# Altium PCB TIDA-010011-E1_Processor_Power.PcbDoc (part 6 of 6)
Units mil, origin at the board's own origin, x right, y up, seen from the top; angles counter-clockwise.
Board outline 4921.26 x 4921.26 mil, 4 copper layers (Top Layer, Gnd layer, Gnd/Pwr layer, Bottom Layer), stack 62.634 mil thick; 631 components, 254 nets, 1751 pads, 757 vias.
Unrouted connection lines stored in the file: 1.
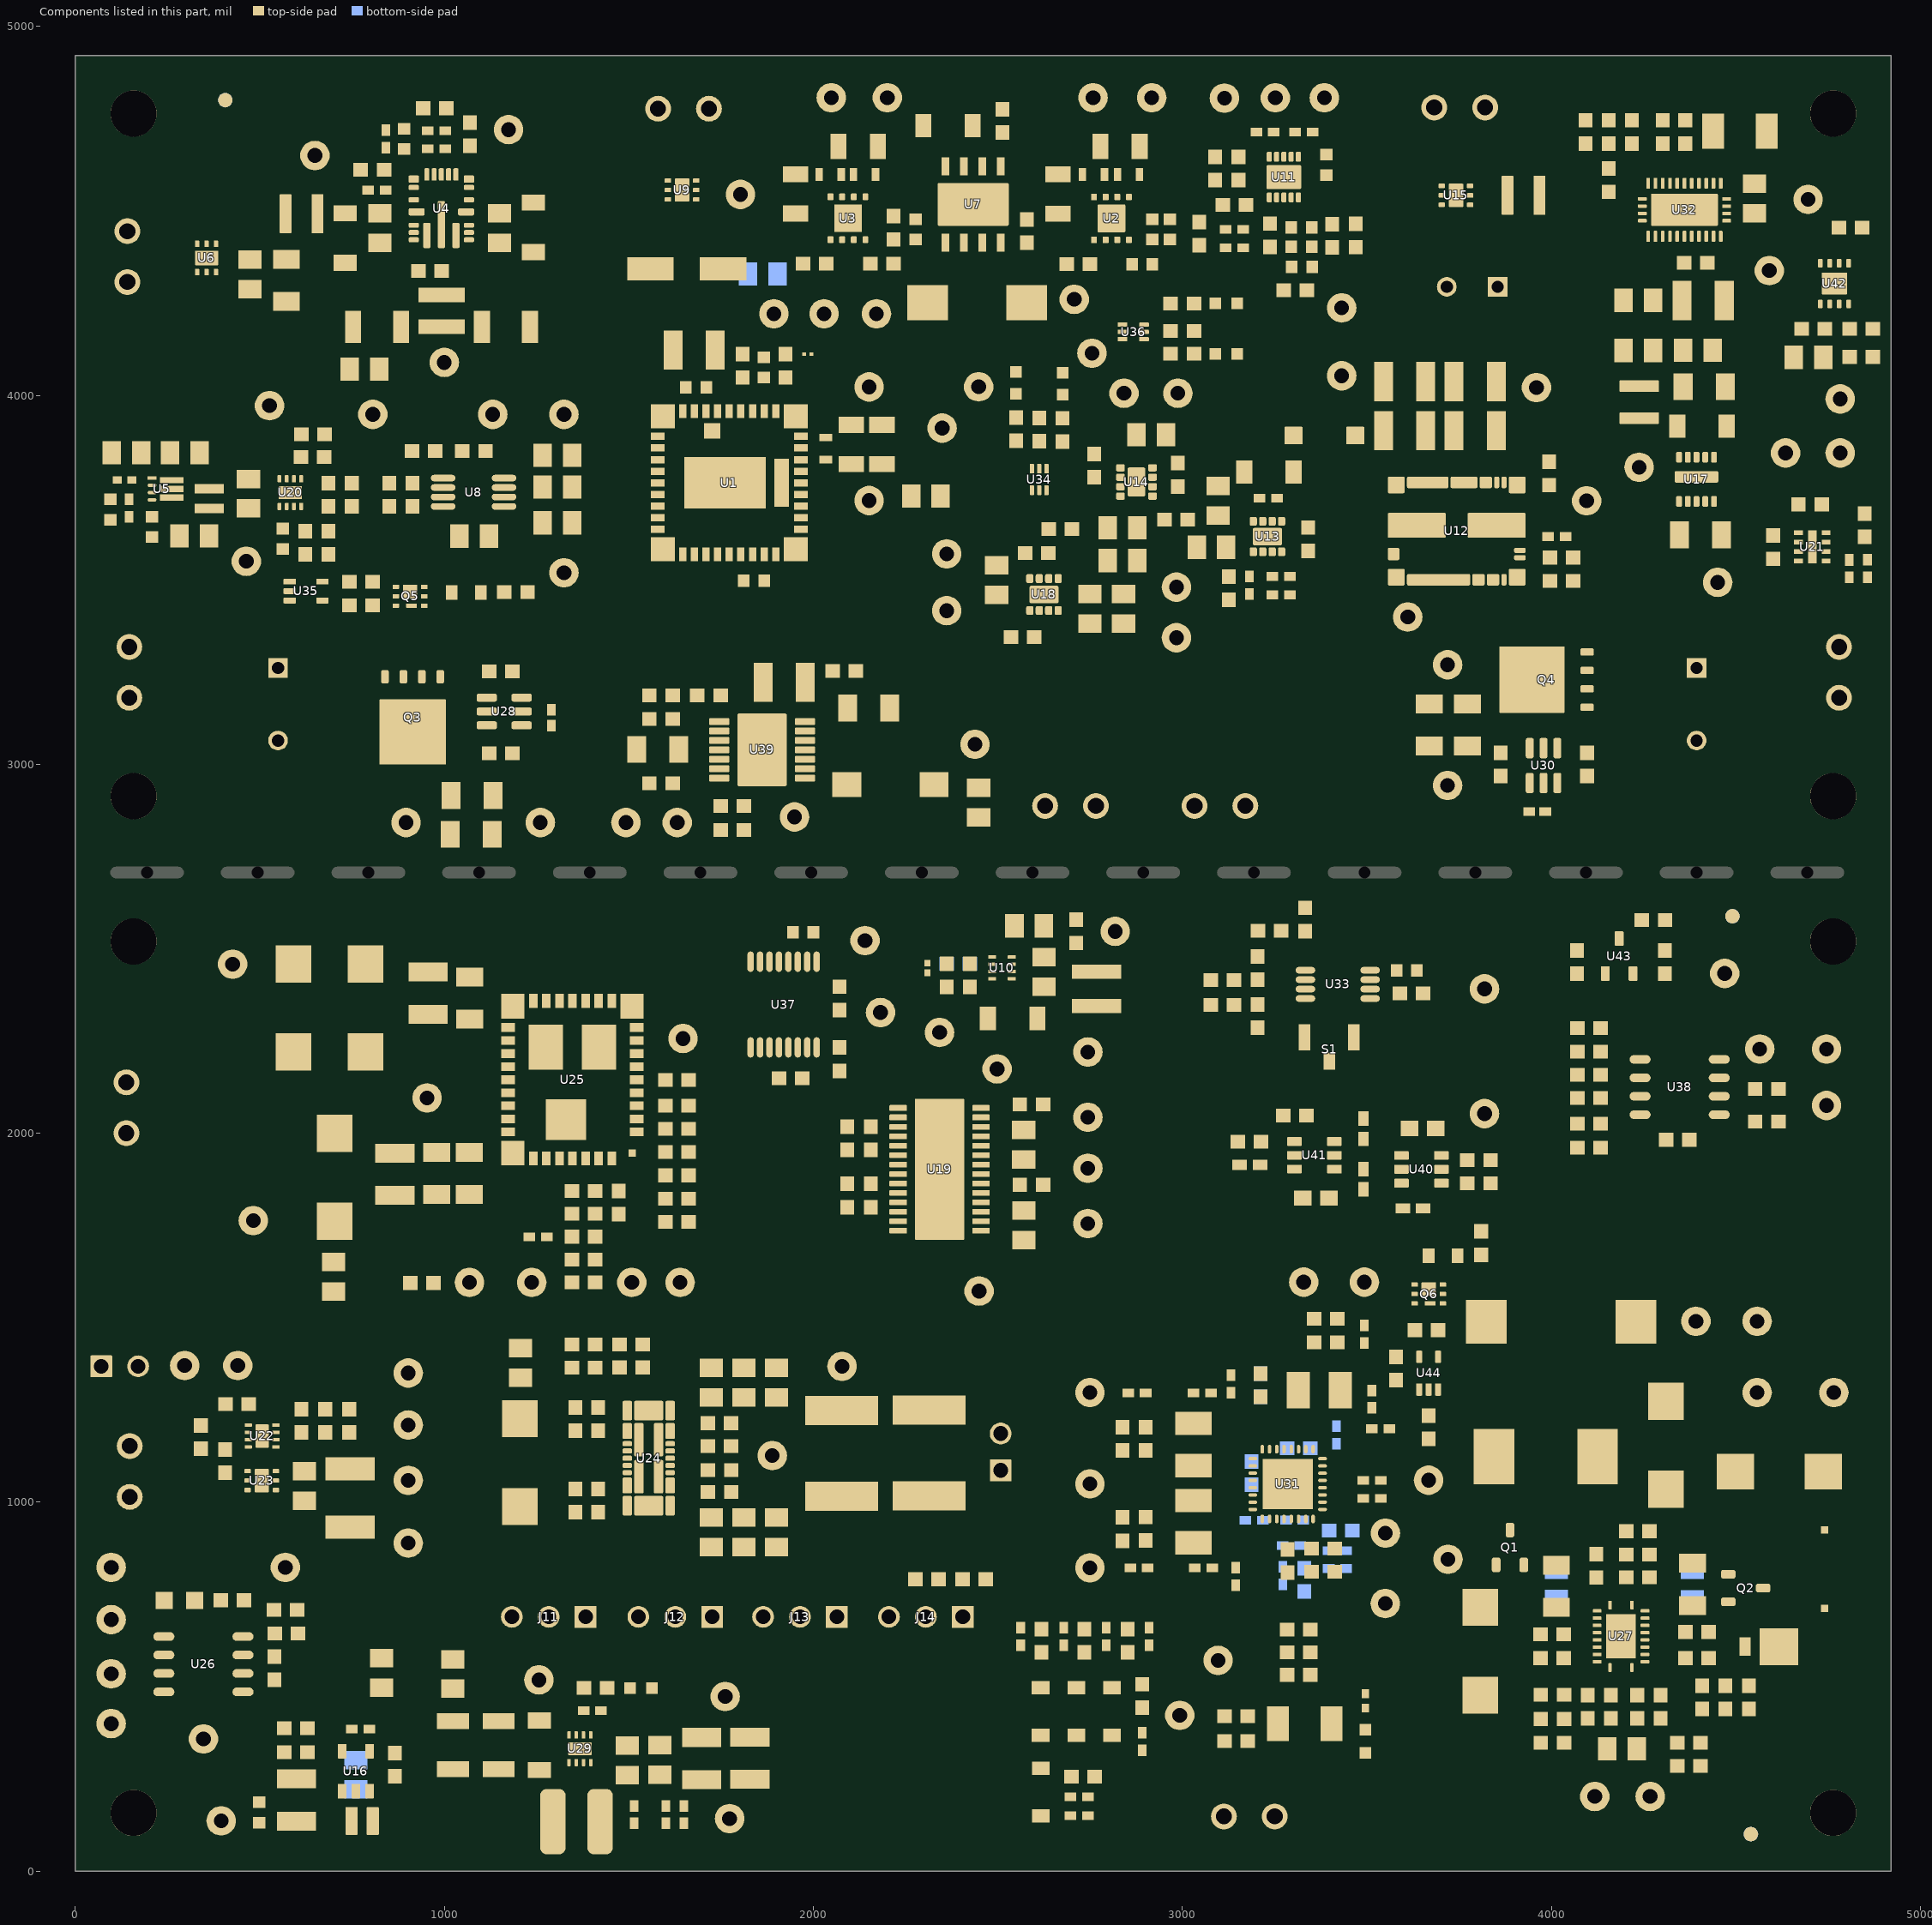
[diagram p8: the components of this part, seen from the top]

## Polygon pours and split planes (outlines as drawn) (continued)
5I_3P3V on Top Layer "n" (solid, remove dead copper, pour order 104): 4593,3827 4593,3723 4618,3698 4644,3672 4644,3658 4644,3624 4647,3621 4682,3621 4684,3623 4684,3668.66 4691,3675.66 4691,3885 4682,3894 4601,3894 4593,3886
NetC149_2 on Top Layer "n" (solid, pour order 108): 22 vertices, not listed, extent 4336,4558 4468,4803.5
GND on Top Layer "n" (solid, remove dead copper, pour order 110): 33 vertices, not listed, extent 4126,4199 4643,4576
3.3V_H on Top Layer "gn" (solid, pour order 200): 511,3743 421,3743 418,3746 418,3900 425,3907 515,3907 522,3900 522,3749 516,3743
5V_EFUSE_OUT on Top Layer "gn" (solid, remove dead copper, pour order 260): 30 vertices, not listed, extent 593,552 1093,1596
GND_5V on Top Layer "gn" (solid, remove dead copper, pour order 262): 4540,554 4534,548 4531,545 4482,545 4413,545 4405,553 4405,671 4414,680 4415,681 4500,681 4532,681 4540,673
NetC74_1 on Top Layer "gn" (solid, remove dead copper, pour order 304): 21 vertices, not listed, extent 3350,1130 3464,1525
GND_5V on Top Layer "gn" (solid, remove dead copper, pour order 306): 3379,1489 3379,1637 3372,1644 3283,1644 3277,1638 3277,1414 3281,1410 3374,1410 3379,1415
NetL13_1 on Top Layer "gn" (solid, remove dead copper, pour order 308): 3343,1387 3288,1387 3283,1382 3278,1377 3278,1321 3278,1240 3296,1222 3341.56,1222 3345.9,1226.34 3349,1229.44 3349,1277 3349,1382 3344,1387
PMIC_IN on Top Layer "gn" (solid, remove dead copper, pour order 310): 3325,330 3325,889 3328,892 3379,892 3379,769 3474,674 3474,530 3461,517 3461,329 3456.84,324.84 3330.16,324.84
NetL14_1 on Top Layer "gn" (solid, pour order 324): 2985.21,1130.25 3107.75,1130.25 3113,1125 3113,1071 3108,1066 2956,1066 2951,1071 2951,1127.54 2953.72,1130.25
NetL10_1 on Top Layer "gn" (solid, pour order 340): 1312,225 1258,225 1252,219 1252,47 1258,41 1264,35 1328,35 1333,40 1333,204 1318,219
NetC129_1 on Top Layer "gn" (solid, pour order 342): 55 vertices, not listed, extent 815,2762 4036,3424
24V_S on Top Layer "gn" (solid, pour order 344): 23 vertices, not listed, extent 3807,3748 4222,4623
1.2V/1A on Top Layer "gn" (solid, pour order 388): 2585,2346 2687,2346 2692,2351 2692,2371 2695,2374 2847,2374 2853,2368 2853,2198 2823,2168 2646,2168 2597,2217 2583,2231 2583,2294 2583,2344
GND_5V on Top Layer "gn" (solid, pour order 390): 26 vertices, not listed, extent 2287,2231 2661,2425
GND_5V on Top Layer "gn" (solid, pour order 396): 2205,2553 2205,2503 2216,2492 2285,2492 2312.26,2519.26 2400.74,2519.26 2493.67,2519.26 2498,2523.58 2498,2557 2490,2565 2217,2565
NetC7_1 on Top Layer "gn" (solid, pour order 398): 2316,3684 2316,3826 2326,3836 2441,3836 2453,3824 2453,3663 2447.67,3657.67 2322.33,3657.67 2316,3664
NetC67_1 on Top Layer "gn" (solid, pour order 400): 1247,1388 1126,1388 1120,1394 1118,1396 1118,1401 1118,1476 1127,1485 1280,1485 1294,1471 1294,1396 1286,1388
NetC186_1 on Top Layer "vo" (solid, pour order 404): 778,385 778,515 789,526 894,526 905,515 905,310 895,300 784,300 778,306
5V_EFUSE_OUT on Top Layer "vo" (solid, pour order 406): 975,552 789,552 779,562 779,622 786,629 951,629 968,646 973,651 990,651 990,552 989,551
NetL19_1 on Top Layer "vo" (solid, pour order 408): 783,204 783,84 788,79 831,79 835,83 835,219 812.02,241.98 787.98,241.98 783,237
GND on Bottom Layer "n" (solid, remove dead copper, pour order 384): 675,2759 40,2759 20.39,2778.61 20.39,4855.65 63.74,4899 4837,4899 4894,4842 4894,2820 4833,2759 4338,2759
GND on Bottom Layer "n" (solid, remove dead copper, pour order 376): 32 vertices, not listed, extent 1434.67,3686.67 1871.67,4832.67
NetC1_1 on Bottom Layer "n" (solid, remove dead copper, pour order 354): 30 vertices, not listed, extent 1673.67,3859.12 1853,4832.67
GND on Bottom Layer "n" (solid, remove dead copper, pour order 368): 49 vertices, not listed, extent 3536,3476 3930.71,4837
NetJ3_1 on Bottom Layer "n" (solid, pour order 360): 3770,4687 3770,4800 3770,4825 3779,4834 3782,4837 3832,4837 3891.34,4837 3899.34,4829 3899.34,4483.34 3893,4477 3775,4477 3770,4482
GND_5V on Bottom Layer "gn" (solid, remove dead copper, pour order 338): 915,2644 42,2644 23,2625 23,50 42,31 4842,31 4899,88 4899,2603 4858,2644
NetC177_1 on Bottom Layer "gn" (solid, remove dead copper, pour order 336): 17 vertices, not listed, extent 3155,109 3289,482
NetC18_1 on Bottom Layer "n" (solid, remove dead copper, pour order 328): 22 vertices, not listed, extent 80,4339 619.38,4576
NetC145_1 on Bottom Layer "gn" (solid, remove dead copper, pour order 188): 1780,1914 1979,1715 2023,1715 2112,1715 2119,1722 2119,1816 2115,1820 2113,1822 2021,1822 1891,1952 1891,2099 1880,2110 1788,2110 1780,2102
AGND on Bottom Layer "n" (solid, remove dead copper, pour order 40): 23 vertices, not listed, extent 1508.67,3465.67 2012.67,3648.67
NetC20_1 on Bottom Layer "n" (solid, remove dead copper, pour order 16): 597,4706 1072,4706 1138,4640 1283,4640 1296,4627 1296,4573 1296,4470 1288,4462 1112.74,4462 1045,4529.74 916.94,4529.74 605.26,4529.74 591,4544 591,4700
12VOUT on Bottom Layer "n" (solid, remove dead copper, pour order 88): 24 vertices, not listed, extent 3378,3600 3721,4109
5V on Bottom Layer "n" (solid, remove dead copper, pour order 28): 2206.67,3657.67 1899.67,3657.67 1894.06,3663.27 1894.06,3851.25 1930.09,3851.25 1938.67,3842.67 1938.67,3799.33 1950,3788 2208,3788 2224.67,3771.33 2224.67,3675.67
24V_S on Bottom Layer "n" (solid, remove dead copper, pour order 248): 18 vertices, not listed, extent 3807.68,3748 4043,4623
GND_5V on Gnd layer "gn" (solid, remove dead copper, pour order 274): 915,2644 42,2644 23,2625 23,50 42,31 4842,31 4899,88 4899,2603 4858,2644
GND on Gnd layer "n" (solid, remove dead copper, pour order 142): 675,2759 40,2759 20.39,2778.61 20.39,4855.65 63.74,4899 4837,4899 4894,4842 4894,2820 4833,2759 4338,2759
GND on Gnd/Pwr layer "gn" (solid, remove dead copper, pour order 370): 40,2759 20.39,2778.61 20.39,3324 74,3377.61 1382.61,3377.61 1433,3428 1433,4882 1450,4899 4836.65,4899 4894,4841.65 4894,2820 4833,2759 40,2759
NetC7_1 on Gnd/Pwr layer "gn" (solid, remove dead copper, pour order 0): 18 vertices, not listed, extent 1894.06,3658 2995,4895.77
GND on Gnd/Pwr layer "n" (solid, remove dead copper, pour order 362): 49 vertices, not listed, extent 3536,3476 3930.71,4837
NetJ3_1 on Gnd/Pwr layer "n" (solid, pour order 358): 3770,4687 3770,4800 3770,4825 3779,4834 3782,4837 3832,4837 3891.34,4837 3899.34,4829 3899.34,4483.34 3893,4477 3775,4477 3770,4482
GND on Gnd/Pwr layer "n" (solid, remove dead copper, pour order 356): 32 vertices, not listed, extent 1434.67,3686.67 1871.67,4832.67
NetC1_1 on Gnd/Pwr layer "n" (solid, remove dead copper, pour order 352): 30 vertices, not listed, extent 1673.67,3859.12 1858.67,4832.67
5V_H on Gnd/Pwr layer "gn" (solid, remove dead copper, pour order 202): 1383,4028 33,4028 21,4040 21,4889.26 31.74,4900 1400,4900 1410,4890 1410,4055
3.3V_H on Gnd/Pwr layer "gn" (solid, remove dead copper, pour order 212): 69,4004 22,3957 22,3450 41,3431 74,3398 862,3398 1366,3398 1411,3443 1411,3976 1383,4004
AGND on Gnd/Pwr layer "n" (solid, pour order 224): 23 vertices, not listed, extent 1508.67,3465.67 2012.67,3648.67
12VOUT on Gnd/Pwr layer "n" (solid, remove dead copper, pour order 228): 24 vertices, not listed, extent 3378,3600 3721,4109
24V_S on Gnd/Pwr layer "n" (solid, remove dead copper, pour order 240): 18 vertices, not listed, extent 3807.68,3748 4043,4623
SVC_5V on Gnd/Pwr layer "n" (solid, remove dead copper, pour order 252): 20 vertices, not listed, extent 4510,4479 4749,4819
5I_3P3V on Gnd/Pwr layer "gn" (solid, remove dead copper, pour order 258): 4593,3886 4593,3491 4605,3479 4630,3479 4890,3479 4901,3490 4901,3902 4890,3913 4603,3913 4593,3903
PMIC_IN on Gnd/Pwr layer "gn" (solid, remove dead copper, pour order 312): 17 vertices, not listed, extent 2537,31 4899,1697
3.6I_3P3V on Gnd/Pwr layer "gn" (solid, remove dead copper, pour order 316): 17 vertices, not listed, extent 1783,1495 4899,2644
NetC67_1 on Gnd/Pwr layer "gn" (solid, pour order 326): 18 vertices, not listed, extent 23,31 2665,2644

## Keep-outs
Keep-Out Layer:
  the board outline again, w10
  text ".Layer_Name" at 179.39,-1385.08 h60

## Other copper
Top Layer:
  text ".Layer_Name" at 179.39,-1385.08 h60
Gnd layer:
  text "'.Layer_Name'" at 200,-1380 h60
Gnd/Pwr layer:
  pour cut-out: 2528,4566 2537,4557 2537,4479 2524,4466 2327,4466 2320,4473 2320,4561 2325,4566
  pour cut-out: 2137.29,4261.23 2200.7,4261.23 2208.5,4253.44 2208.5,4193.44 2195.5,4180.44 2141.5,4180.44 2128.5,4193.44 2128.5,4252.44
  pour cut-out: 4751.79,3883.05 4815.21,3883.05 4823,3875.25 4823,3815.25 4810,3802.25 4756,3802.25 4743,3815.25 4743,3874.25
  pour cut-out: 2726.86,4845.79 2790.28,4845.79 2798.07,4838 2798.07,4778 2785.07,4765 2731.07,4765 2718.07,4778 2718.07,4837
  pour cut-out: 2014.79,4846.79 2078.21,4846.79 2086,4839 2086,4779 2073,4766 2019,4766 2006,4779 2006,4838
  pour cut-out: 2201.67,4096.67 2212.67,4085.67 2212.67,3950.67 2199.67,3937.67 1996.67,3937.67 1983.67,3950.67 1983.67,4090.67 1989.67,4096.67
  text "'.Layer_Name'" at 207,-1387 h60
Bottom Layer:
  text ".Layer_Name" at 179.39,-1385.08 h60

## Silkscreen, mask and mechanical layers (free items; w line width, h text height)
Top Overlay:
  lines w6: 286.31,3791.54 303.54,3791.54 ; 525,3651 525,3666 537.01,3678.01 537.01,3693.94 ; 713.27,3790.24 713.27,3794.27 726,3807 726,3813 ; 746.65,3616.35 746.65,3539 835,3539 ; 748,3643 748,3657 879,3657 879,3553 ; 757,3633 729,3633 ; 833.98,3521.53 843.53,3521.53 ; 918,4817 918,4863 ; 1151,3202.06 1151,3084.95 1170.95,3084.95 1170.95,3202 1151.05,3202 ; 1869,4017 1869,4024 ; 2409,4061 2409,4074 ; 2665,2351 2665,2363 ; 2694.6,4133.4 2703.5,4133.4 ; 2741.71,4207.71 2741.71,4217.31 ; 2752,3597 2764,3609 2764,3612 ; 3090,4301 3090,4366 ; 3124.92,4674.45 3124.92,4684.92 ; 3198,4846 3208,4836 ; 3238,4312 3236,4310 ; 3266,4154 3266,4242 ; 3368,4484 3368,4490 3284,4490 3273,4479 3273,4347 3236,4310 ; 3375,4364 3375,4250 3361,4236 3361,4062 3236,4062 3236,4270 3236,4310 ; 3392,766 3392,783 ; 3692,1009 3731,970 3769,970 ; 4071.8,504.98 4071.8,520.2 4345.2,520.2 4364,539 4903,539 4903,367 4578,367 4559.98,385.02 4323.2,385.02 ; 4146,952 4158,940 4158,894 4166.8,885.2 4175.02,885.2 ; 4294.98,754.02 4294.98,768.8 ; 4630,396 4581,396 ; 729,3633 729,3631 736,3624 736,3640 729,3633 ; 918,4863 919,4863 925,4857 912,4857 918,4863 ; 3090,4366 3096,4360 3084,4360 3090,4366 ; 3266,4242 3267,4242 3275,4234 3258,4234 3266,4242 ; 3392,783 3387,778 3399,778 3394,783 3392,783 ; 4581,396 4589,388 4589,404 4581,396 ; 3919.95,2990.58 4038,2990.58 4038.06,2990.64 4038.06,3010.53 3919.95,3010.53 3919.95,2990.58
  lines w10: 194,2706.42 -0.42,2706.42 4920.42,2706.42
  text "1.8V" at 2873,4873 h30
  text "3.3V" at 2157,4871 h30
  text "GND" at 2698,4871 h30
  text "DDR_REF" at 3340,4870 h30
  text "GND" at 2007,4869 h30
  text "PG3" at 3069,4866 h30
  text "EN" at 3198,4846 h30 r90
  text "RESET" at 1236,4710 h30
  text "SVC_5V" at 4650,4594 h30
  text "GND" at 4519,4400 h30
  text "VTT_DDR" at 3387,4301 h30
  text "UVLO" at 1883,4288 h30 r90
  text "PG2" at 1992,4283 h30
  text "GND" at 2132,4283 h30
  text "VREF" at 2641,4170 h30
  text "12VOUT" at 3370.74,4116.58 h30
  text "PG1" at 2623,4115 h30
  text "VSENSE" at 2345,4083 h30
  text "5V_H" at 946,3995 h30
  text "GND" at 2240,3986 h30 r90
  text "SD" at 2319,3973 h30
  text "1.2V_CPM" at 3054,3964 h30
  text "GND" at 2781,3943 h30 r90
  text "3.3V_H" at 867,3939 h30
  text "5I_3P3V" at 4542,3906 h30
  text "FLAG1" at 1415,3904 h30 r90
  text "FLAG2" at 1221,3898 h30 r90
  text "GND" at 4873,3805 h30 r90
  text "PG4" at 4202,3711 h30
  text "5V" at 2112,3618 h30
  text "1.8V_CPM" at 2094,3501 h30
  text "FLAG3" at 1285,3423 h30
  text "SW" at 3481,3399 h30
  text "GND" at 2220,3359 h30
  text "GND" at 3571,2925.53 h30
  text "GND" at 748,2819 h30
  text "GND" at 2042,2812 h30 r90
  text "'.PRJ_Number'" at 3277,2766 h50
  text "PM_2.5V_OUT" at 317,2568 h30
  text "PG" at 2882,2532 h30
  text "SS/TR" at 1583,2355 h30
  text "RESET2" at 3686,2295 h30
  text "ALERT" at 4484,2289 h30
  text "EN" at 2163,2234 h30
  text "SCL" at 4812,2215 h30
  text "1.2V/1A" at 2809,2188 h30
  text "GND_5V" at 2156,2186 h30
  text "RESET1" at 2281,2128 h30
  text "GND_5V" at 717,2096 h30
  text "SDA" at 4810,2063 h30
  text "3.3I_1P8V" at 2812,2029 h30
  text "GND_5V" at 2805,1844 h30
  text "5V_EFUSE" at 251,1836 h30
  text "GND_5V" at 3213,1663 h30
  text "PMIC_1V5" at 3399,1662 h30
  text "3.6I_3P3V" at 2697,1648 h30
  text "GND_5V" at 4496,1597 h30
  text "VOUT1" at 4328,1592 h30
  text "RT/CLK" at 1704,1583 h30
  text "GND_5V" at 2516,1555 h30
  text "VADJ" at 1458,1504 h30
  text "UVLO" at 240,1474 h30
  text "DV/DT" at 386,1474 h30
  text "PG" at 1037,1468 h30
  text "INH" at 1205,1467 h30
  text "VOUT2" at 4708,1402 h30
  text "PMIC_3V3" at 2628,1367 h30
  text "PM_3.6V_OUT" at 2144,1352 h30
  text "ILM" at 967,1299 h30
  text "GND_5V" at 4487,1222 h30 r90
  text "GND_5V" at 1815,1186 h25
  text "FLT" at 966,1158 h30
  text "GND_5V" at 2525,987 h30
  text "5V_EFUSE" at 836,965 h30
  text "PMIC_RESET" at 3783,954 h30
  text "PMIC_IN" at 3631,907 h30
  text "PMIC_1V1" at 2476,849 h30
  text "GND_5V" at 846,796 h30
  text "PMIC_1V8_1" at 3487,741.73 h25 r90
  text "PG_2A" at 1184,584 h30
  text "GND_5V" at 3027,538 h30 r90
  text "GND_5V" at 1823,471 h30
  text "PMIC_1V8_2" at 3587,432 h25 r90
  text "GND_5V" at 3880,204 h30
  text "VCC_1.8V_2A" at 1840,109 h30
  text "VOUT3" at 4211,104 h30
  text "3.3V" at 302,39 h30
  text "'.PRJ_Number'" at 1541,31 h50
  text ".Layer_Name" at 179.39,-1385.08 h60
Bottom Overlay:
  text ".Layer_Name" at 179.39,-1385.08 h60
Top Paste:
  text ".Layer_Name" at 179.39,-1385.08 h60
Bottom Paste:
  text ".Layer_Name" at 179.39,-1385.08 h60
Top Solder:
  text ".Layer_Name" at 179.39,-1385.08 h60
  text ".Layer_Name" at 179.39,-1385.08 h60
Bottom Solder:
  text ".Layer_Name" at 179.39,-1385.08 h60
Drill Guide:
  text ".Layer_Name" at 179.39,-1385.08 h60
M1 Board Outline:
  the board outline again, w10
M2 Board Dimensions:
  rectangle: -397.61,-801.58 -272.61,-676.58
  rectangle: -272.61,-926.58 102.39,-801.58
  lines w7: -397.61,-801.58 602.39,-801.58 ; -272.61,-926.58 -272.61,-676.58 ; -147.61,-926.58 -147.61,-676.58 ; 102.39,-926.58 102.39,-676.58 ; 352.39,-926.58 352.39,-676.58 ; -397.61,-926.58 602.39,-926.58 602.39,-676.58 -397.61,-676.58 -397.61,-926.58
M3 3D STEP Top:
  text ".Layer_Name" at 179.39,-1385.08 h60
M4 3D STEP Bottom:
  text ".Layer_Name" at 179.39,-1385.08 h60
M5 Assembly Top:
  circle w10: c3642,1289 r3.16
  circle w10: c720,199 r4.24
  circle w10: c4146,2414 r8
  circle w6: c3354,2259 r8.06
  circle w6: c3851,873 r7.07
  circle w6: c4518,804 r7.07
  circle w6: c564,3496 r7.07
  circle w6: c1029,3779 r7.07
  lines w6: 1045.54,3676.24 1045.54,3798.28 1112.46,3798.28 1112.46,3676.24 1045.54,3676.24 ; 3755.11,1421.7 4298.89,1421.7 4298.89,1556.3 3755.11,1556.3 3755.11,1421.7
  lines w10: -689.61,-1456.75 5910.39,-1456.75 ; -689.61,-1253.42 5912.39,-1253.42 ; -689.61,-1050.08 -689.61,-1660.08 3315.39,-1660.08 5912.39,-1660.08 5912.39,-1050.08 -689.11,-1050.08 -689.11,-1660.08 886.39,-1660.08 ; 1775.39,-1660.08 1775.39,-1050.08 ; 3042.39,-1253.42 3042.39,-1050.08 ; 3882.39,-1253.42 3882.39,-1050.08 ; 4504.39,-1666.58 4504.39,-1463.75
  text "COMPONENTS MARKED 'DNP' SHOULD NOT BE POPULATED." at 755.89,-845.08 h20
  text "ASSEMBLY VARIANT:" at 755.39,-960.58 h20
  text ".VariantName" at 1791.39,-960.58 h20
  text "PCB VIEWED FROM TOP SIDE" at -626.11,-1182.25 h20
  text "BOARD #:" at 1850.39,-1182.25 h20
  text ".PRJ_Number" at 2395.89,-1182.25 h20
  text "REV:" at 3240.39,-1182.25 h20
  text ".PCB_Rev" at 3531.89,-1182.25 h20
  text "SVN REV:" at 4078.39,-1182.25 h20
  text ".VersionControl_RevNumber" at 4584.39,-1182.25 h20
  text "'.Layer_Name'" at 172,-1384 h20
  text "TID #:" at 1850.39,-1385.58 h20
  text ".TID" at 2395.89,-1385.58 h20
  text "LAYER NAME =" at -626.11,-1388.08 h20
  text "PLOT NAME =" at -626.11,-1590.92 h20
  text ".plot_File_Name" at 179.39,-1590.92 h20
  text "GENERATED    :" at 1852.39,-1590.92 h20
  text ".Print_Date" at 2721.89,-1590.92 h20
  text ".Print_Time" at 3450.89,-1590.92 h20
  text "TEXAS INSTRUMENTS" at 4715.39,-1590.92 h20
M6 Assembly Bottom:
  lines w10: -690.11,-1253.92 5911.89,-1253.92 ; -688.11,-1457.25 5911.89,-1457.25 ; 717.89,-1667.08 717.89,-1464.25 ; 1339.89,-1253.92 1339.89,-1050.58 ; 2179.89,-1253.92 2179.89,-1050.58 ; 3446.89,-1660.58 3446.89,-1050.58 ; 4335.89,-1660.58 5911.39,-1660.58 5911.39,-1050.58 -690.11,-1050.58 -690.11,-1660.58 1906.89,-1660.58 5911.89,-1660.58 5911.89,-1050.58
  text "COMPONENTS MARKED 'DNP' SHOULD NOT BE POPULATED." at 5704.39,-844.58 h20
  text ".VariantName" at 4660.39,-960.58 h20
  text "ASSEMBLY VARIANT:" at 5699.39,-960.58 h20
  text ".VersionControl_RevNumber" at 637.89,-1182.75 h20
  text "SVN REV:" at 1143.89,-1182.75 h20
  text ".PCB_Rev" at 1690.39,-1182.75 h20
  text "REV:" at 1981.89,-1182.75 h20
  text ".PRJ_Number" at 2826.39,-1182.75 h20
  text "BOARD #:" at 3371.89,-1182.75 h20
  text "PCB VIEWED FROM BOTTOM SIDE" at 5848.39,-1182.75 h20
  text "'.Layer_Name'" at 4638,-1375 h20
  text "LAYER NAME =" at 5497,-1386 h20
  text ".TID" at 2826.39,-1386.08 h20
  text "TID #:" at 3371.89,-1386.08 h20
  text "TEXAS INSTRUMENTS" at 506.89,-1591.42 h20
  text ".Print_Time" at 1771.39,-1591.42 h20
  text ".Print_Date" at 2500.39,-1591.42 h20
  text "GENERATED    :" at 3369.89,-1591.42 h20
  text ".plot_File_Name" at 5042.89,-1591.42 h20
  text "PLOT NAME =" at 5848.39,-1591.42 h20
M9 Title Sheet:
  drawing of 57 lines, arcs and shapes, not listed
  text "1" at 342.22,7509.92 h70
  text "2" at 2837.89,7509.92 h70
  text "3" at 5327.23,7509.92 h70
  text "4" at 7833.9,7509.92 h70
  text "5" at 10332.89,7509.92 h70
  text "6" at 12837.89,7509.92 h70
  text "A" at -814.11,6366.92 h70
  text "A" at 13985.89,6366.92 h70
  text "A" at 13987.91,6366.14 h70
  text "B" at -814.11,3986.92 h70
  text "B" at 13985.89,3986.92 h70
  text "B" at 13987.91,3986.14 h70
  text "C" at -814.11,1611.92 h70
  text "C" at 13985.89,1611.92 h70
  text "C" at 13987.91,1611.14 h70
  text "PROJECT TITLE:" at 10945.89,-249.08 h45
  text ".PRJ_Title" at 10995.89,-382.41 h70
  text "DESIGNED FOR:" at 10945.89,-550.08 h45
  text ".PRJ_Customer" at 10995.89,-690.08 h70
  text "D" at -814.11,-758.08 h70
  text "D" at 13985.89,-758.08 h70
  text "FILE NAME:" at 10945.89,-850.08 h45
  text ".PCB_File_Name_No_Path" at 10995.89,-970.08 h70
  text "Texas Instruments (TI) and/or its licensors do not warrant the accuracy or completeness of this specification" at 5976.39,-1131.92 h45
  text "ENGINEER:" at 10945.89,-1140.08 h45
  text "LAYOUT BY:" at 12450.89,-1140.08 h45
  text "or any information contained therein. TI and/or its licensors do not warrant that this design will meet" at 5931.4,-1244.59 h45
  text ".PRJ_Engineer" at 10995.89,-1295.08 h70
  text ".PCB_Layout" at 12501.39,-1295.08 h70
  text "the specifications, will be suitable for your application or fit for any particular purpose, or will operate in" at 5931.4,-1357.25 h45
  text "ALTIUM DESIGNER VERSION:" at 12450.89,-1450.08 h45
  text "an implementation. TI and/or its licensors do not warrant that the design is production worthy. You should" at 5931.4,-1469.92 h45
  text "completely validate and test your design implementation to confirm the system functionality for your application." at 5976.39,-1582.58 h45
  text ".print_Scale" at 10995.89,-1583.41 h70
  text ".Application_BuildNumber" at 12501.39,-1583.41 h70
  text "1" at 342.22,-1790.08 h70
  text "2" at 2837.89,-1790.08 h70
  text "3" at 5327.23,-1790.08 h70
  text "4" at 7833.9,-1790.08 h70
  text "5" at 10332.89,-1790.08 h70
  text "6" at 12837.89,-1790.08 h70
M10 Fab Notes:
  drawing of 227 lines, arcs and shapes, not listed
  text "DESIGN INFORMATION" at 11973.86,6273.36 h60
  text "(REFER ALSO ARRAY/PANEL PROFILING INFORMATION)" at 11622.35,6107.29 h60
  text "BOARD SIZE" at 10936.35,6103 h60
  text "125MM" at 12059.37,5984.64 h60
  text "125MM" at 11312.37,5982.64 h60
  text "X" at 11904.35,5975.18 h60
  text "Number of Layers :" at 11339.34,5778 h60
  text "4" at 12411.89,5773 h60
  text "8" at 12412.82,5641.2 h60
  text "MIN. TRACK WIDTH:" at 11339.34,5639 h60
  text "MIL" at 12590.34,5639 h60
  text "5.9" at 12351,5509 h60
  text "MIN. CLEARANCE:" at 11339.34,5507 h60
  text "MIL" at 12590.34,5507 h60
  text "MIN. VIA DRILL SIZE:" at 11339.34,5375 h60
  text "7.874" at 12277.82,5375.2 h60
  text "MIL" at 12590.34,5375 h60
  text "4.925MIL" at 12034.35,5233.29 h60
  text "MINIMUM ANNULAR RING" at 11010.11,5229 h60
  text "EXTERNAL" at 12925.89,5218 h60
  text "PER" at 11210.11,5111 h60
  text "IPC-D-275 CLASS 2 LEVEL C" at 11430.11,5111 h60
  text "+/-" at 12525.89,4998 h60
  text "MIL, HOLES" at 12918.34,4998.71 h60
  text "+/-" at 13379.89,4998 h60
  text "REGISTRATION TOLERANCES:" at 11010.11,4993 h60
  text "METAL" at 12209.89,4993 h60
  text "5" at 12786.09,4993 h60
  text "3" at 13619.09,4993 h60
  text "MIL" at 13735.34,4993 h60
  text "MATERIAL:" at 10935.35,4783.54 h60
  text "FR-4 High Tg" at 11921.79,4643.21 h60
  text "X" at 11762.89,4635 h60
  text "FR-408" at 11356.35,4634.64 h60
  text "OTHER" at 12844.35,4634.64 h60
  text "63 MIL (1.6mm) +/-10%" at 11676.45,4471.92 h60
  text "THICKNESS:" at 11010.11,4467.64 h60
  text "X" at 11548.28,4467.64 h60
  text "OTHER" at 12961.35,4467.64 h60
  text "TOLERANCE:" at 11010.11,4309.64 h60
  text "X" at 11849.42,4309.64 h60
  text "ANSI IPC-6012 TYPE 3 CLASS 2" at 12036.36,4309.64 h60
  text "OTHER +/-" at 12036.35,4153.64 h60
  text "BOW & TWIST:" at 11010.11,3996.64 h60
  text "X" at 11849.42,3996.64 h60
  text "ANSI IPC-6012 TYPE 3 CLASS 2" at 12036.36,3996.64 h60
  text "OTHER +/-" at 12036.35,3838.13 h60
  text "COPPER THICKNESS (FINISHED):" at 10935.35,3702.64 h60
  text "1.4MIL (1oz)" at 11815.34,3549.92 h60
  text "2MIL (1.4oz)" at 12582.35,3549.92 h60
  text "2.8MIL (2oz)" at 13309.35,3549.92 h60
  text "OUTER:" at 11292.35,3545.64 h60
  text "X" at 11686.89,3545 h60
  text "X" at 11682.89,3395 h60
  text "1.4MIL (1oz)" at 11815.34,3392.92 h60
  text "2.8MIL (2oz)" at 12582.35,3392.92 h60
  text "N/A" at 13308.89,3393.29 h60
  text "INNER SIGNAL:" at 11003.26,3388.64 h60
  text "DRILLING:" at 10935.35,3249.64 h60
  text "REFERENCE:" at 11010.11,3132.64 h60
  text "X" at 11658.35,3132.64 h60
  text "AS SHOWN" at 11845.34,3132.64 h60
  text "X" at 12559.35,3132.64 h60
  text "NC_DRILL FILES" at 12696.34,3132.64 h60
  text "PTH MIN COPPER THICKNESS:" at 11010.11,2974.64 h60
  text "X" at 12360.35,2974.64 h60
  text "1MIL" at 12497.34,2974.64 h60
  text "OTHER" at 12994.35,2974.64 h60
  text "BOARD FINISH:" at 10935.35,2815.64 h60
  text "SILKSCREEN:" at 11090.57,2697.64 h60
  text "X" at 12039.35,2697.64 h60
  text "TOP" at 12165.34,2697.64 h60
  text "X" at 12549.35,2697.64 h60
  text "BOTTOM" at 12676.34,2697.64 h60
  text "SILKSCREEN COLOR:" at 11090.57,2530.64 h60
  text "X" at 12038.3,2530.64 h60
  text "WHITE" at 12165.34,2530.64 h60
  text "OTHER" at 12676.34,2530.64 h60
  text "SOLDER RESIST COLOR:" at 11090.57,2360.64 h60
  text "X" at 11658.31,2201.44 h60
  text "GREEN" at 11785.34,2201.44 h60
  text "BLUE" at 12376.34,2201.44 h60
  text "OTHER" at 12914.35,2201.44 h60
  text "IMMERSION GOLD (ENIG)" at 11996.34,2012.92 h60
  text "ENEPIG" at 13333.89,2009.64 h60
  text "SURFACE FINISH:" at 10935.35,2008.64 h60
  text "X" at 11809.4,2008.64 h60
  text "IMM. TIN/SILVER OR EQUIV" at 11264.89,1851.64 h60
  text "OTHER" at 12696.35,1851.64 h60
  text "ARRAY/PANEL:" at 10935.35,1672.64 h60
  text "CUT AND TRIM PER MECH LAYER 1" at 11996.35,1668.35 h60
  text "N.C. ROUTE" at 11996.34,1516.64 h60
  text "X" at 12675.35,1516.64 h60
  text "V. SCORE" at 12862.35,1516.64 h60
  text "CERTIFICATION:" at 10935.35,1379.64 h60
  text "MATERIALS AND WORKMANSHIP FOR ALL PCBS" at 11660.35,1379.64 h60
  text "TO MEET OR EXCEED THE REQUIREMENTS OF:" at 11660.35,1281.64 h60
  text "X" at 11286.85,1145.13 h60
  text "ANSI IPC-A-600F CLASS ->" at 11425.85,1145.13 h60
  text "X" at 13064.9,1145.13 h60
  text "2" at 13183.85,1145.14 h60
  text "1" at 12868.85,1143.64 h60
  text "3" at 13537.85,1143.64 h60
  text "X" at 11288.9,985.64 h60
  text "UL 94V-0" at 11425.85,985.64 h60
  text "X" at 12100.9,985.64 h60
  text "RoHS" at 12237.85,985.64 h60
  text "OTHER" at 12882.25,985.64 h60
  text "PER ORDER" at 13279.31,985.64 h60
  text "VIA TENTING:" at 12152.89,852 h60
  text "X" at 12915.37,848.64 h60
  text "ADDITIONAL REQUIREMENTS:" at 10935.35,844.64 h60
  text "YES" at 12702.55,842.92 h60
  text "NO" at 13067.36,837.69 h60
  text "MICROSECTION:" at 11010.11,729.64 h60
  text "YES" at 11915.85,729.64 h60
  text "IMPEDANCE CONTROL:" at 12174.89,723 h60
  text "YES" at 13158.89,722 h60
  text "X" at 13700.89,715 h60
  text "NO" at 13534.36,704.69 h60
  text "REQUIRED" at 12777.34,573.49 h60
  text "BARE BOARD ELEC. TEST:" at 11010.11,570.64 h60
  text "NONE" at 12315.85,570.64 h60
  text "X" at 12650.35,570.64 h60
  text "PER ORDER" at 13369.35,570.64 h60
  text "MANUFACTURER'S UL:" at 11010.11,413.64 h60
  text "RAIL" at 12175.85,409.35 h60
  text "METAL" at 12667.66,409.35 h60
  text "X" at 13042.89,409 h60
  text "SILK" at 13179.34,409.35 h60
M11 Gerber Information:
  lines w10: -689.61,-1456.75 5910.39,-1456.75 ; -689.61,-1253.42 5912.39,-1253.42 ; -689.61,-1050.08 -689.61,-1660.08 3315.39,-1660.08 5912.39,-1660.08 5912.39,-1050.08 -689.11,-1050.08 -689.11,-1660.08 886.39,-1660.08 ; 1775.39,-1660.08 1775.39,-1050.08 ; 3042.39,-1253.42 3042.39,-1050.08 ; 3882.39,-1253.42 3882.39,-1050.08 ; 4504.39,-1666.58 4504.39,-1463.75
  text ".PRJ_Number" at 2309,-1174 h25
  text "ALL ARTWORK VIEWED FROM TOP SIDE" at -626.11,-1182.25 h60
  text "BOARD #:" at 1850.39,-1182.25 h60
  text "REV:" at 3240.39,-1182.25 h60
  text ".PCB_Rev" at 3531.89,-1182.25 h60
  text "SVN REV:" at 4078.39,-1182.25 h60
  text ".VersionControl_RevNumber" at 4584.39,-1182.25 h60
  text "LAYER NAME =" at -626.11,-1385.08 h60
  text "TID #:" at 1850.39,-1385.58 h60
  text ".TID" at 2395.89,-1385.58 h60
  text ".plot_File_Name" at 70,-1577 h25
  text "PLOT NAME =" at -626.11,-1590.92 h60
  text "GENERATED    :" at 1852.39,-1590.92 h60
  text ".Print_Date" at 2721.89,-1590.92 h60
  text ".Print_Time" at 3450.89,-1590.92 h60
  text "TEXAS INSTRUMENTS" at 4715.39,-1590.92 h60
M12 Stackup:
  drawing of 295 lines, arcs and shapes, not listed
  text "Layer" at 5266.5,3573.5 h60
  text "Name" at 5676.41,3573.5 h60
  text "Material" at 6606.16,3573.5 h60
  text "Thickness" at 7465.92,3573.5 h60
  text "Constant" at 8115.76,3573.5 h60
  text "Board Layer Stack" at 8685.62,3573.5 h60
  text "1" at 5266.5,3453.5 h60
  text "Top Overlay" at 5676.41,3453.5 h60
  text "2" at 5266.5,3333.5 h60
  text "Top Solder" at 5676.41,3333.5 h60
  text "Solder Resist" at 6606.16,3333.5 h60
  text "0.30mil" at 7465.92,3333.5 h60
  text "3.5" at 8115.76,3333.5 h60
  text "3" at 5266.5,3213.5 h60
  text "Top Layer" at 5676.41,3213.5 h60
  text "Copper" at 6606.16,3213.5 h60
  text "1.40mil" at 7465.92,3213.5 h60
  text "4" at 5266.5,3093.5 h60
  text "Dielectric1" at 5676.41,3093.5 h60
  text "FR-4 High Tg" at 6606.16,3093.5 h60
  text "16.00mil" at 7465.92,3093.5 h60
  text "4.2" at 8115.76,3093.5 h60
  text "5" at 5266.5,2973.5 h60
  text "Gnd layer" at 5676.41,2973.5 h60
  text "Copper" at 6606.16,2973.5 h60
  text "1.42mil" at 7465.92,2973.5 h60
  text "6" at 5266.5,2853.5 h60
  text "Dielectric 2" at 5676.41,2853.5 h60
  text "FR-4 High Tg" at 6606.16,2853.5 h60
  text "25.00mil" at 7465.92,2853.5 h60
  text "4.5" at 8115.76,2853.5 h60
  text "7" at 5266.5,2733.5 h60
  text "Gnd/Pwr layer" at 5676.41,2733.5 h60
  text "Copper" at 6606.16,2733.5 h60
  text "1.42mil" at 7465.92,2733.5 h60
  text "8" at 5266.5,2613.5 h60
  text "Dielectric 3" at 5676.41,2613.5 h60
  text "FR-4 High Tg" at 6606.16,2613.5 h60
  text "16.00mil" at 7465.92,2613.5 h60
  text "4.2" at 8115.76,2613.5 h60
  text "9" at 5266.5,2493.5 h60
  text "Bottom Layer" at 5676.41,2493.5 h60
  text "Copper" at 6606.16,2493.5 h60
  text "1.40mil" at 7465.92,2493.5 h60
  text "10" at 5266.5,2373.5 h60
  text "Bottom Solder" at 5676.41,2373.5 h60
  text "Solder Resist" at 6606.16,2373.5 h60
  text "0.30mil" at 7465.92,2373.5 h60
  text "3.5" at 8115.76,2373.5 h60
  text "11" at 5266.5,2253.5 h60
  text "Bottom Overlay" at 5676.41,2253.5 h60
M13 Component Bodies Top:
  text ".Layer_Name" at 179.39,-1385.08 h60
M14 Component Bodies Bottom:
  text ".Layer_Name" at 179.39,-1385.08 h60
M15 Courtyards Top:
  text ".Layer_Name" at 179.39,-1385.08 h60
M16 Courtyards Bottom:
  text ".Layer_Name" at 179.39,-1385.08 h60
Drill Drawing:
  circle w10: c3630.62,6145.28 r33.33
  circle w10: c3630.62,5995.27 r20
  circle w10: c3630.62,5995.27 r33.33
  lines w10: 3597.29,5528.61 3613.96,5528.61 3613.96,5511.94 3647.29,5511.94 3647.29,5528.61 3663.96,5528.61 3663.96,5561.94 3647.29,5561.94 3647.29,5578.61 3613.96,5578.61 3613.96,5561.94 3597.29,5561.94 3597.29,5528.61 ; 3597.29,5661.94 3663.96,5661.94 3663.96,5728.61 3597.29,5728.61 3597.29,5661.94 ; 3597.29,5845.27 3630.62,5811.94 3663.96,5845.27 3630.62,5878.61 3597.29,5845.27 ; 3597.29,6261.94 3663.96,6261.94 3663.96,6328.61 3597.29,6328.61 3597.29,6261.94 ; 3597.29,6411.94 3630.62,6428.61 3663.96,6411.94 3647.29,6445.28 3663.96,6478.61 3630.62,6461.94 3597.29,6478.61 3613.96,6445.28 3597.29,6411.94 ; 3597.29,6578.61 3613.96,6578.61 3630.62,6561.94 3647.29,6578.61 3663.96,6578.61 3647.29,6595.28 3663.96,6611.94 3647.29,6611.94 3630.62,6628.61 3613.96,6611.94 3597.29,6611.94 3613.96,6595.28 3597.29,6578.61 ; 3597.29,6778.61 3663.96,6778.61 3630.62,6711.94 3597.29,6778.61 ; 3610.62,6275.28 3650.62,6275.28 3650.62,6315.28 3610.62,6315.28 3610.62,6275.28
  lines w15: 3537.5,5466.94 8272.22,5466.94 ; 3537.5,6816.94 8272.22,6816.94 ; 4088.38,5316.94 4088.38,6966.94 ; 4688.22,5316.94 4688.22,6966.94 ; 5827.88,5316.94 5827.88,6966.94 ; 6333.76,5316.94 6333.76,6966.94 ; 7067.56,5316.94 7067.56,6966.94 ; 3537.5,5316.94 8272.22,5316.94 8272.22,6966.94 3537.5,6966.94 3537.5,5316.94
  text "Symbol" at 3627.5,6861.94 h72
  text "Count" at 4133.38,6861.94 h72
  text "Hole Size" at 4733.22,6861.94 h72
  text "Plated" at 5872.88,6861.94 h72
  text "Hole Type" at 6378.76,6861.94 h72
  text "Hole Length" at 7112.56,6861.94 h72
  text "210" at 4133.38,6711.94 h60
  text "7.87mil (0.200mm)" at 4733.22,6711.94 h60
  text "PTH" at 5872.88,6711.94 h60
  text "Round" at 6378.76,6711.94 h60
  text "-" at 7112.56,6711.94 h60
  text "35" at 4133.38,6561.94 h60
  text "8.00mil (0.203mm)" at 4733.22,6561.94 h60
  text "PTH" at 5872.88,6561.94 h60
  text "Round" at 6378.76,6561.94 h60
  text "-" at 7112.56,6561.94 h60
  text "112" at 4133.38,6411.94 h60
  text "12.00mil (0.305mm)" at 4733.22,6411.94 h60
  text "PTH" at 5872.88,6411.94 h60
  text "Round" at 6378.76,6411.94 h60
  text "-" at 7112.56,6411.94 h60
  text "400" at 4133.38,6261.94 h60
  text "16.00mil (0.406mm)" at 4733.22,6261.94 h60
  text "PTH" at 5872.88,6261.94 h60
  text "Round" at 6378.76,6261.94 h60
  text "-" at 7112.56,6261.94 h60
  text "16" at 4133.38,6111.94 h60
  text "32.00mil (0.813mm)" at 4733.22,6111.94 h60
  text "NPTH" at 5872.88,6111.94 h60
  text "Slot" at 6378.76,6111.94 h60
  text "200.00mil (5.080mm)" at 7112.56,6111.94 h60
  text "6" at 4133.38,5961.94 h60
  text "33.47mil (0.850mm)" at 4733.22,5961.94 h60
  text "PTH" at 5872.88,5961.94 h60
  text "Round" at 6378.76,5961.94 h60
  text "-" at 7112.56,5961.94 h60
  text "127" at 4133.38,5811.94 h60
  text "40.00mil (1.016mm)" at 4733.22,5811.94 h60
  text "PTH" at 5872.88,5811.94 h60
  text "Round" at 6378.76,5811.94 h60
  text "-" at 7112.56,5811.94 h60
  text "20" at 4133.38,5661.94 h60
  text "43.31mil (1.100mm)" at 4733.22,5661.94 h60
  text "PTH" at 5872.88,5661.94 h60
  text "Round" at 6378.76,5661.94 h60
  text "-" at 7112.56,5661.94 h60
  text "8" at 4133.38,5511.94 h60
  text "125.00mil (3.175mm)" at 4733.22,5511.94 h60
  text "NPTH" at 5872.88,5511.94 h60
  text "Round" at 6378.76,5511.94 h60
  text "-" at 7112.56,5511.94 h60
  text "934 Total" at 4133.38,5361.94 h60
  text "Slot definitions :" at 3627.5,5216.97 h60
  text "Routed Path Length" at 4660.19,5216.97 h60
  text "= Calculated from tool start centre position to tool end centre position." at 5762.86,5216.97 h60
  text "Hole Length" at 4660.19,5116.99 h60
  text "= Routed Path Length + Tool Size = Slot length as defined in the PCB layout" at 5352.99,5116.99 h60
  text "Drill Table" at 5101.77,4833 h60
  text "FOR 7.874MIL DRILL +0/-7.874MIL" at 5102,4697 h60
  text "FOR 8MIL DRILL +0/-8MIL" at 5102,4603 h60
  text "FOR 12MIL DRILL +0/-12MIL" at 5102,4514 h60
  text "FOR 16MIL DRILL +0/-16MIL" at 5101.77,4425 h60
  text "FOR PTH DRILL +/-3MIL" at 5097.51,4338.45 h60
  text "FOR NPTH DRILL +/-2MIL" at 5101.77,4255 h60
  text "Note:-" at 5102,4063 h60
  text "7.874MIL Vias alone are not tented." at 5437,3965 h60
  text ".Layer_Name" at 179.39,-1385.08 h60
M17 Embedded Cavity:
  text ".Layer_Name" at 179.39,-1385.08 h60
M18 Embedded Assembly:
  text ".Layer_Name" at 179.39,-1385.08 h60
M19 Embedded Keepout:
  text ".Layer_Name" at 179.39,-1385.08 h60

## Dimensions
0,0 to 0,4921.26 on M2 Board Dimensions
0,0 to 4921.26,0 on M2 Board Dimensions
-397.61,-926.58 to 602.39,-926.58 on M2 Board Dimensions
